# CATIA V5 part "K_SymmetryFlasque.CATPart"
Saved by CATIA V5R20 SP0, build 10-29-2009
Part number: Symmetry of Flasque
Bounding box of the stored display mesh (mm): x -5 to 320, y 0 to 255, z -118 to 60
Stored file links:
  G:\Khaled_CFAO_2011\SIL\SIL_GR2\zthiebault\Khaled\CAD_ThinkMOTION\K_SymmetryFlasque.CATPart
  G:\Khaled_CFAO_2011\SIL\SIL_GR2\zthiebault\Khaled\CAD_ThinkMOTION\K_Flasque.CATPart
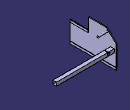
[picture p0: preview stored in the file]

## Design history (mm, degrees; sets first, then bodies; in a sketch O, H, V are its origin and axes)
Body1 (main body)
  Body2 "Corps du corps principal d'origine"
    Solid1: linked copy from another document
  Assemble1: tool Body2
